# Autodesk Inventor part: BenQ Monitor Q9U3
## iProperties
Created: 2004-08
Part Number: BenQ Monitor Q9U3
Document SubType Name: Modeling
Designer: RSC
Manufacturer: Standard
Standards Organization: Custom
Author: RSC
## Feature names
1. Extrusion1
2. Extrusion2
3. Fase1 [Chamfer]
4. Rundung1 [Fillet]
5. Extrusion4
6. Bohrung1 [Hole]
7. Extrusion5
8. Bohrung2 [Hole]
9. Extrusion3
10. Flächenverjüngung1
11. Extrusion6
12. Rundung2 [Fillet]
13. Extrusion7
